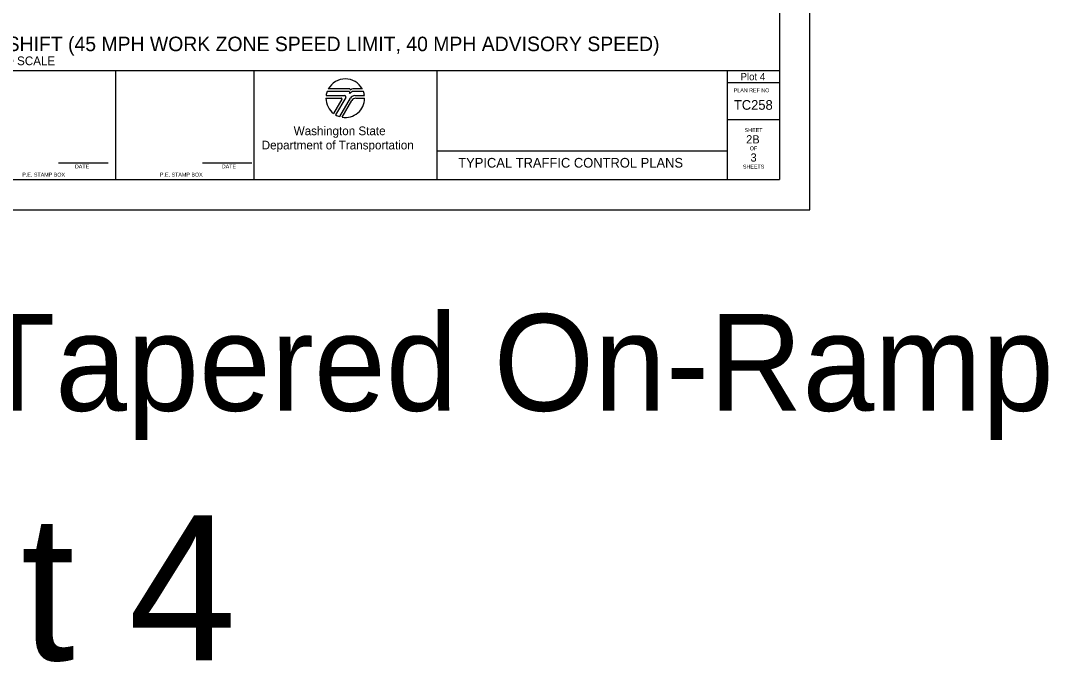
# Model space of a CAD drawing. Extents: x 99999 to 100116, y 99995 to 100013.
# Drawn here: x 100067.9 to 100078.53, y 99995.01 to 100001.64 of the extents above; entities that cross this region are included whole.
import ezdxf

# ---------------------------------------------------------------- set-up
doc = ezdxf.new("R2010")
doc.units = 0
for name, color, linetype in [('SH_DE_DetailHeading1Text', 7, 'Continuous'), ('SH_GI_PlotLimits', 7, 'Continuous'), ('SH_GI_SheetBorder', 7, 'Continuous'), ('SH_GI_SheetLocationText', 7, 'Continuous'), ('SH_GI_SheetTextInCells', 7, 'Continuous'), ('SH_GI_TitleBlockText', 7, 'Continuous'), ('SH_GI_WSDOTLogo', 7, 'Continuous')]:
    doc.layers.add(name, color=color, linetype=linetype)

msp = doc.modelspace()

# ---------------------------------------------------------------- linework, layer by layer
at = {"layer": 'SH_GI_PlotLimits'}
msp.add_lwpolyline([(100059.062, 99999.687), (100076.062, 99999.687), (100076.062, 100010.687), (100059.062, 100010.687)], close=True, dxfattribs=at)
at = {"layer": 'SH_GI_SheetBorder'}
for p, q in [((100075.75, 100010.375), (100075.75, 100000)), ((100060, 100001.126), (100075.75, 100001.126)), ((100068.883, 100000), (100068.883, 100001.126)), ((100070.309, 100001.126), (100070.309, 100000)), ((100072.205, 100001.126), (100072.205, 100000)), ((100075.208, 100001.126), (100075.208, 100000)), ((100075.208, 100001.001), (100075.75, 100001.001)), ((100075.208, 100000.618), (100075.75, 100000.618)), ((100072.205, 100000.295), (100075.208, 100000.295)), ((100068.29, 100000.173), (100068.802, 100000.173)), ((100069.78, 100000.173), (100070.291, 100000.173)), ((100060, 100000), (100075.75, 100000))]:
    msp.add_line(p, q, dxfattribs=at)
at = {"layer": 'SH_GI_WSDOTLogo'}
for p, q in [((100071.303, 100000.935), (100071.081, 100000.935)), ((100071.433, 100000.935), (100071.335, 100000.935)), ((100071.057, 100000.84), (100071.215, 100000.84)), ((100071.059, 100000.866), (100071.25, 100000.866)), ((100071.289, 100000.909), (100071.07, 100000.909)), ((100071.222, 100000.828), (100071.136, 100000.681)), ((100071.261, 100000.846), (100071.157, 100000.667)), ((100071.199, 100000.649), (100071.309, 100000.839)), ((100071.445, 100000.909), (100071.343, 100000.909)), ((100071.343, 100000.909), (100071.343, 100000.909)), ((100071.356, 100000.866), (100071.456, 100000.866)), ((100071.365, 100000.839), (100071.457, 100000.839)), ((100071.224, 100000.643), (100071.324, 100000.816))]:
    msp.add_line(p, q, dxfattribs=at)
for centre, radius, start, end in [((100071.257, 100000.84), 0.2, 28.4787, 151.532), ((100071.303, 100000.926), 0.00903, 329.8742, 90.0033), ((100071.335, 100000.907), 0.0287, 90.0072, 148.1676), ((100071.257, 100000.84), 0.2, 179.9986, 232.8433), ((100071.257, 100000.84), 0.2, 159.696, 172.5057), ((100071.215, 100000.832), 0.0082, 329.7436, 90), ((100071.257, 100000.84), 0.2, 260.5455, 359.8086), ((100071.25, 100000.853), 0.0131, 329.7683, 90), ((100071.289, 100000.895), 0.0148, 327.8418, 89.9985), ((100071.343, 100000.861), 0.0484, 89.9953, 147.8238), ((100071.356, 100000.812), 0.0542, 90, 149.9974), ((100071.365, 100000.792), 0.0476, 90, 150.0543), ((100071.257, 100000.84), 0.2, 7.4943, 20.2941), ((100071.257, 100000.84), 0.2, 239.7929, 253.0448)]:
    msp.add_arc(centre, radius, start, end, dxfattribs=at)

# ---------------------------------------------------------------- texts
at = {"layer": 'SH_DE_DetailHeading1Text'}
for s, height, p in [("FREEWAY (2 LANES): SINGLE RIGHT LANE CLOSURE, 9' MAX LEFT SHOULDER SHIFT (45 MPH WORK ZONE SPEED LIMIT, 40 MPH ADVISORY SPEED)", 0.15, (100060.091, 100001.326)), ('NOT TO SCALE', 0.09, (100067.373, 100001.181))]:
    msp.add_text(s, height=height, rotation=360, dxfattribs=at).set_placement(p)
at = {"layer": 'SH_GI_SheetBorder'}
msp.add_text('PLAN REF NO', height=0.04003, dxfattribs=at).set_placement((100075.275, 100000.901))
at = {"layer": 'SH_GI_SheetLocationText'}
for s, height, p in [('Plot 4', 0.075, (100075.345, 100001.025)), ('Right Ramps: Tapered On-Ramp', 1, (100058.967, 99997.607)), ('Plot 4', 1.5, (100065.001, 99995.027))]:
    msp.add_text(s, height=height, dxfattribs=at).set_placement(p)
at = {"layer": 'SH_GI_SheetTextInCells'}
for s, height, p in [('Washington State', 0.09007, (100070.723, 100000.457)), ('SHEET', 0.04, (100075.388, 100000.49)), ('Department of Transportation', 0.09007, (100070.392, 100000.31)), ('OF', 0.04, (100075.441, 100000.301)), ('DATE', 0.04, (100068.46, 100000.114)), ('DATE', 0.04, (100069.979, 100000.114)), ('SHEETS', 0.04, (100075.37, 100000.112)), ('P.E. STAMP BOX', 0.04003, (100067.915, 100000.029)), ('P.E. STAMP BOX', 0.04003, (100069.339, 100000.029))]:
    msp.add_text(s, height=height, dxfattribs=at).set_placement(p)
at = {"layer": 'SH_GI_TitleBlockText'}
for s, height, p in [('TC258', 0.1, (100075.277, 100000.72)), ('2B', 0.085, (100075.404, 100000.372)), ('TYPICAL TRAFFIC CONTROL PLANS', 0.1, (100072.425, 100000.122)), ('3', 0.085, (100075.449, 100000.184))]:
    msp.add_text(s, height=height, dxfattribs=at).set_placement(p)

doc.saveas('drawing.dxf')
